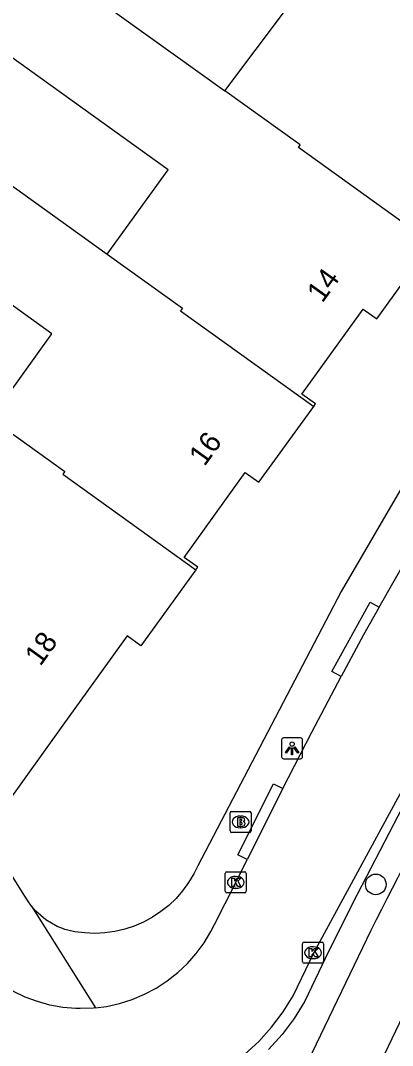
# Model space of a CAD drawing. Extents: x 158838 to 160074, y 386376 to 387776.
# Drawn here: x 159225.69 to 159243.35, y 386797.89 to 386846.63 of the extents above; entities that cross this region are included whole.
import ezdxf

# ---------------------------------------------------------------- set-up
doc = ezdxf.new("R2010")
doc.units = 0
for name, color, linetype in [('IMGEO_Boom', 7, 'Continuous'), ('IMGEO_Brandkraan', 7, 'Continuous'), ('IMGEO_Fietspad_gesloten', 7, 'Continuous'), ('IMGEO_Haag', 7, 'Continuous'), ('IMGEO_Kolk', 7, 'Continuous'), ('IMGEO_Lichtpunt', 7, 'Continuous'), ('IMGEO_Pand', 7, 'Continuous'), ('IMGEO_Pand_nummerreeks', 7, 'Continuous'), ('IMGEO_Rijbaan_lokaal_open', 7, 'Continuous'), ('IMGEO_Voetpad_open', 7, 'Continuous')]:
    doc.layers.add(name, color=color, linetype=linetype)

msp = doc.modelspace()

# ---------------------------------------------------------------- linework, layer by layer
at = {"layer": 'IMGEO_Boom'}
msp.add_circle((159242.563, 386805.553), 0.489, dxfattribs=at)
at = {"layer": 'IMGEO_Brandkraan'}
for p, q in [((159235.715, 386809.022), (159236.567, 386809.022)), ((159235.64, 386808.096), (159235.64, 386808.948)), ((159236.128, 386808.802), (159236.153, 386808.802)), ((159236.641, 386808.948), (159236.641, 386808.096)), ((159236.567, 386808.022), (159235.715, 386808.022)), ((159236.151, 386808.242), (159236.126, 386808.242))]:
    msp.add_line(p, q, dxfattribs=at)
for points in [[(159235.715, 386809.022), (159236.567, 386809.022)], [(159235.64, 386808.096), (159235.64, 386808.948)], [(159235.988, 386808.722), (159235.988, 386808.322), (159236.201, 386808.322)], [(159236.219, 386808.722), (159235.988, 386808.722)], [(159236.167, 386808.641), (159236.113, 386808.641), (159236.113, 386808.565)], [(159236.113, 386808.565), (159236.166, 386808.565)], [(159236.175, 386808.489), (159236.113, 386808.489), (159236.113, 386808.408)], [(159236.641, 386808.948), (159236.641, 386808.096)], [(159236.567, 386808.022), (159235.715, 386808.022)], [(159236.113, 386808.408), (159236.175, 386808.408)]]:
    msp.add_lwpolyline(points, dxfattribs=at)
for centre, radius, start, end in [((159235.717, 386808.946), 0.0765, 91.552, 178.448), ((159235.717, 386808.946), 0.0765, 91.552, 178.448), ((159236.565, 386808.946), 0.0765, 1.552, 88.448), ((159236.565, 386808.946), 0.0765, 1.552, 88.448), ((159236.168, 386808.603), 0.0379, 267.8285, 90.9355), ((159236.176, 386808.448), 0.0404, 269.8759, 90.5077), ((159236.223, 386808.577), 0.145, 59.4692, 91.5367), ((159236.248, 386808.624), 0.0922, 285.5137, 58.1501), ((159236.253, 386808.432), 0.105, 301.3115, 78.989), ((159235.717, 386808.098), 0.0765, 181.552, 268.448), ((159235.717, 386808.098), 0.0765, 181.552, 268.448), ((159236.207, 386808.573), 0.251, 268.6676, 293.5347), ((159236.565, 386808.098), 0.0765, 271.552, 358.448), ((159236.565, 386808.098), 0.0765, 271.552, 358.448)]:
    msp.add_arc(centre, radius, start, end, dxfattribs=at)
for centre, major_axis, ratio, start_param, end_param in [((159236.127, 386808.522), (-0.387, 0.002), 0.722429, 4.712389, 7.853982), ((159236.152, 386808.522), (-0.39, 0.002), 0.717154, 1.570796, 4.712389)]:
    msp.add_ellipse(centre, major_axis=major_axis, ratio=ratio, start_param=start_param, end_param=end_param, dxfattribs=at)
at = {"layer": 'IMGEO_Fietspad_gesloten'}
for points in [[(159242.326, 386803.363), (159238.334, 386795.064), (159235.594, 386789.49), (159235.091, 386788.626)], [(159242.073, 386795.583), (159244.248, 386800.111)]]:
    msp.add_lwpolyline(points, dxfattribs=at)
msp.add_arc((159443.078, 386703.143), 224.378, 148.90963, 153.47047, dxfattribs=at)
at = {"layer": 'IMGEO_Haag'}
msp.add_lwpolyline([(159273.392, 386853.651), (159260.53, 386835.762), (159256.863, 386830.685), (159255.079, 386828.194), (159253.364, 386825.663), (159251.714, 386823.086), (159250.404, 386820.929), (159248.07, 386816.93), (159245.802, 386812.886), (159243.604, 386808.803), (159241.476, 386804.683), (159240.155, 386802.033), (159239.189, 386800.003), (159238.681, 386799.182), (159238.109, 386798.417), (159237.471, 386797.706)], dxfattribs=at)
at = {"layer": 'IMGEO_Kolk'}
for p, q in [((159235.413, 386805.225), (159235.413, 386806.077)), ((159235.488, 386806.151), (159236.34, 386806.151)), ((159236.414, 386806.077), (159236.414, 386805.225)), ((159235.901, 386805.931), (159235.926, 386805.931)), ((159236.34, 386805.151), (159235.488, 386805.151)), ((159235.924, 386805.371), (159235.899, 386805.371)), ((159239.081, 386801.881), (159239.081, 386802.733)), ((159239.156, 386802.807), (159240.008, 386802.807)), ((159240.082, 386802.733), (159240.082, 386801.881)), ((159239.569, 386802.587), (159239.594, 386802.587)), ((159240.008, 386801.807), (159239.156, 386801.807)), ((159239.592, 386802.027), (159239.567, 386802.027))]:
    msp.add_line(p, q, dxfattribs=at)
for points in [[(159235.413, 386805.225), (159235.413, 386806.077)], [(159235.488, 386806.151), (159236.34, 386806.151)], [(159236.414, 386806.077), (159236.414, 386805.225)], [(159235.734, 386805.851), (159235.857, 386805.851), (159235.857, 386805.7), (159235.987, 386805.851), (159236.151, 386805.851), (159236.005, 386805.7), (159236.158, 386805.451), (159236.006, 386805.451), (159235.921, 386805.615), (159235.857, 386805.548), (159235.857, 386805.451), (159235.734, 386805.451), (159235.734, 386805.851)], [(159236.34, 386805.151), (159235.488, 386805.151)], [(159239.081, 386801.881), (159239.081, 386802.733)], [(159239.156, 386802.807), (159240.008, 386802.807)], [(159240.082, 386802.733), (159240.082, 386801.881)], [(159239.402, 386802.507), (159239.525, 386802.507), (159239.525, 386802.356), (159239.655, 386802.507), (159239.819, 386802.507), (159239.673, 386802.356), (159239.826, 386802.107), (159239.674, 386802.107), (159239.589, 386802.271), (159239.525, 386802.204), (159239.525, 386802.107), (159239.402, 386802.107), (159239.402, 386802.507)], [(159240.008, 386801.807), (159239.156, 386801.807)]]:
    msp.add_lwpolyline(points, dxfattribs=at)
for centre, start, end in [((159235.49, 386806.075), 91.552, 178.448), ((159235.49, 386806.075), 91.552, 178.448), ((159236.338, 386806.075), 1.552, 88.448), ((159236.338, 386806.075), 1.552, 88.448), ((159235.49, 386805.227), 181.552, 268.448), ((159235.49, 386805.227), 181.552, 268.448), ((159236.338, 386805.227), 271.552, 358.448), ((159236.338, 386805.227), 271.552, 358.448), ((159239.158, 386802.731), 91.552, 178.448), ((159239.158, 386802.731), 91.552, 178.448), ((159240.006, 386802.731), 1.552, 88.448), ((159240.006, 386802.731), 1.552, 88.448), ((159239.158, 386801.883), 181.552, 268.448), ((159239.158, 386801.883), 181.552, 268.448), ((159240.006, 386801.883), 271.552, 358.448), ((159240.006, 386801.883), 271.552, 358.448)]:
    msp.add_arc(centre, 0.0765, start, end, dxfattribs=at)
for centre, major_axis, ratio, start_param, end_param in [((159235.9, 386805.651), (-0.387, 0.002), 0.722429, 4.712389, 7.853982), ((159235.925, 386805.651), (-0.39, 0.002), 0.717154, 1.570796, 4.712389), ((159239.568, 386802.307), (-0.387, 0.002), 0.722429, 4.712389, 7.853982), ((159239.593, 386802.307), (-0.39, 0.002), 0.717154, 1.570796, 4.712389)]:
    msp.add_ellipse(centre, major_axis=major_axis, ratio=ratio, start_param=start_param, end_param=end_param, dxfattribs=at)
at = {"layer": 'IMGEO_Lichtpunt'}
for p, q in [((159238.089, 386812.426), (159238.089, 386811.619)), ((159238.089, 386812.426), (159238.089, 386811.619)), ((159238.991, 386812.521), (159238.183, 386812.521)), ((159238.991, 386812.521), (159238.183, 386812.521)), ((159239.085, 386811.619), (159239.085, 386812.426)), ((159239.085, 386811.619), (159239.085, 386812.426)), ((159238.183, 386811.525), (159238.991, 386811.525)), ((159238.183, 386811.525), (159238.991, 386811.525))]:
    msp.add_line(p, q, dxfattribs=at)
for points in [[(159238.463, 386812.09), (159238.502, 386812.062), (159238.314, 386811.8), (159238.276, 386811.827), (159238.463, 386812.09)], [(159238.565, 386812.042), (159238.612, 386812.042), (159238.612, 386811.72), (159238.565, 386811.72), (159238.565, 386812.042)], [(159238.675, 386812.062), (159238.713, 386812.089), (159238.9, 386811.827), (159238.861, 386811.799), (159238.675, 386812.062)]]:
    msp.add_lwpolyline(points, dxfattribs=at)
msp.add_circle((159238.588, 386812.224), 0.0994, dxfattribs=at)
for centre, start, end in [((159238.183, 386812.426), 90, 180), ((159238.183, 386812.426), 90, 180), ((159238.991, 386812.426), 0, 90), ((159238.991, 386812.426), 0, 90), ((159238.183, 386811.619), 180, 270), ((159238.183, 386811.619), 180, 270), ((159238.991, 386811.619), 270, 0), ((159238.991, 386811.619), 270, 360)]:
    msp.add_arc(centre, 0.0946, start, end, dxfattribs=at)
at = {"layer": 'IMGEO_Pand'}
for points in [[(159235.399, 386843.28), (159238.363, 386847.237), (159227.886, 386854.768), (159230.926, 386858.231), (159244.539, 386848.455)], [(159229.812, 386835.509), (159232.697, 386839.52), (159221.551, 386847.538), (159224.603, 386851.031), (159225.399, 386850.46)], [(159227.807, 386848.731), (159235.399, 386843.28)], [(159224.29, 386827.709), (159227.178, 386831.724), (159219.709, 386837.119), (159216.473, 386839.444), (159219.15, 386843.17), (159222.395, 386840.838), (159229.812, 386835.509)], [(159245.208, 386836.047), (159238.885, 386840.592), (159238.973, 386840.714), (159235.399, 386843.28)], [(159239.613, 386828.276), (159239.701, 386828.399), (159239.052, 386828.867), (159241.96, 386832.905), (159242.609, 386832.438), (159245.208, 386836.047)], [(159229.812, 386835.509), (159233.382, 386832.944), (159233.294, 386832.822), (159239.613, 386828.276)], [(159234.018, 386820.508), (159234.106, 386820.63), (159233.457, 386821.097), (159236.366, 386825.136), (159237.014, 386824.669), (159239.613, 386828.276)], [(159224.29, 386827.709), (159227.79, 386825.185), (159227.702, 386825.063), (159234.018, 386820.508)], [(159234.018, 386820.508), (159231.411, 386816.899), (159230.762, 386817.366), (159227.71, 386813.123), (159224.017, 386807.989)]]:
    msp.add_lwpolyline(points, dxfattribs=at)
at = {"layer": 'IMGEO_Rijbaan_lokaal_open'}
for points in [[(159231.305, 386794.999), (159233.189, 386795.661), (159234.033, 386796.005), (159234.842, 386796.423), (159235.611, 386796.912), (159236.333, 386797.468), (159237.003, 386798.086), (159237.614, 386798.761), (159238.163, 386799.488), (159238.645, 386800.261), (159238.66, 386800.288), (159239.618, 386802.301), (159249.891, 386821.241), (159250.502, 386822.26), (159256.377, 386831.036), (159260.043, 386836.113), (159272.905, 386854.001), (159286.185, 386872.449), (159287.428, 386874.189), (159288.379, 386875.519)], [(159242.728, 386818.731), (159244.208, 386821.349), (159244.932, 386822.579), (159245.506, 386823.542)], [(159242.728, 386818.731), (159241.985, 386817.426), (159240.919, 386815.431)], [(159238.155, 386810.105), (159239.532, 386812.786), (159240.919, 386815.431)], [(159238.155, 386810.105), (159236.453, 386806.74)], [(159229.253, 386799.685), (159229.783, 386799.755), (159230.398, 386799.893), (159230.998, 386800.084), (159231.579, 386800.329), (159232.135, 386800.625), (159232.663, 386800.969), (159233.158, 386801.359), (159233.616, 386801.791), (159234.033, 386802.263), (159234.407, 386802.77), (159234.734, 386803.309), (159234.908, 386803.648), (159235.91, 386805.65), (159236.453, 386806.74)], [(159229.253, 386799.685), (159229.159, 386799.673), (159228.529, 386799.647), (159228.382, 386799.649), (159228.321, 386799.651), (159227.703, 386799.706), (159227.092, 386799.816), (159226.494, 386799.98), (159225.912, 386800.196), (159225.352, 386800.464), (159224.819, 386800.781), (159224.315, 386801.144), (159223.847, 386801.551), (159223.416, 386801.997), (159223.027, 386802.481), (159222.86, 386802.747)]]:
    msp.add_lwpolyline(points, dxfattribs=at)
at = {"layer": 'IMGEO_Voetpad_open'}
for points in [[(159244.141, 386825.019), (159240.91, 386819.482), (159234.105, 386806.442), (159233.915, 386806.051), (159233.67, 386805.639), (159233.39, 386805.251), (159233.076, 386804.889), (159232.73, 386804.557), (159232.357, 386804.258), (159231.958, 386803.992), (159231.537, 386803.764), (159231.097, 386803.574), (159230.642, 386803.424), (159230.176, 386803.315), (159229.702, 386803.248), (159229.223, 386803.224), (159228.745, 386803.243), (159228.27, 386803.304), (159227.802, 386803.408), (159227.729, 386803.434), (159227.44, 386803.556), (159227.163, 386803.704), (159226.901, 386803.876), (159226.655, 386804.07), (159226.427, 386804.286), (159226.219, 386804.521)], [(159240.919, 386815.431), (159240.481, 386815.671), (159242.29, 386818.971), (159242.728, 386818.731)], [(159236.453, 386806.74), (159236.007, 386806.965), (159237.709, 386810.33), (159238.155, 386810.105)], [(159226.219, 386804.521), (159226.033, 386804.774), (159225.871, 386805.042), (159224.017, 386807.989)], [(159226.219, 386804.521), (159229.253, 386799.685)]]:
    msp.add_lwpolyline(points, dxfattribs=at)

# ---------------------------------------------------------------- texts
at = {"layer": 'IMGEO_Pand_nummerreeks'}
for s, rotation, p in [('14', 54.2419, (159240.024, 386833.161)), ('16', 54.2397, (159234.429, 386825.39)), ('18', 54.272, (159226.632, 386815.885))]:
    msp.add_text(s, height=1, rotation=rotation, dxfattribs=at).set_placement(p)

doc.saveas('drawing.dxf')
